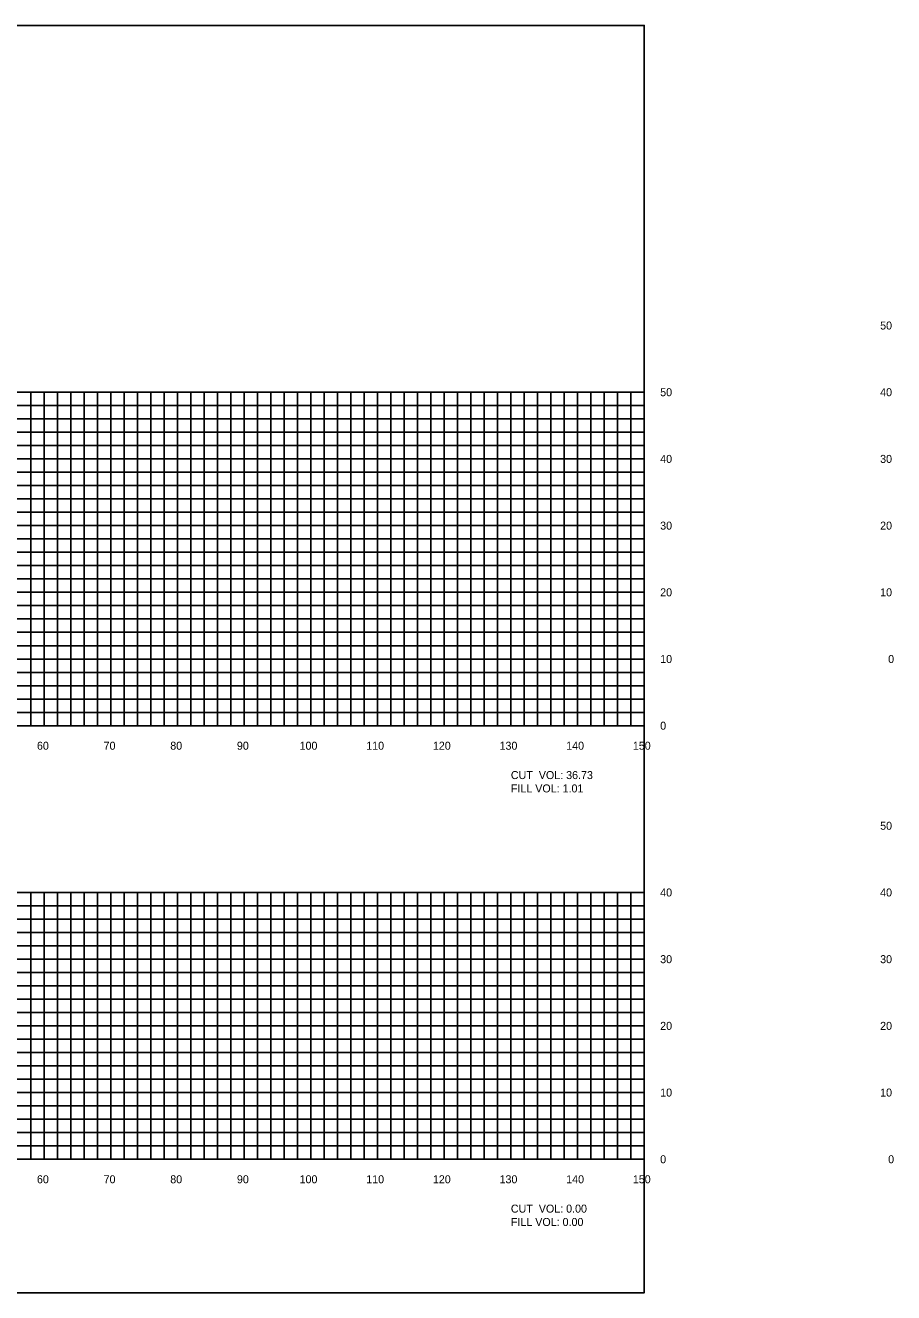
# Model space of a CAD drawing. Extents: x 1797652 to 1804145, y 245981 to 250269.
# Drawn here: x 1802348.2 to 1802478.4, y 250079.4 to 250269.4 of the extents above; entities that cross this region are included whole.
import ezdxf

# ---------------------------------------------------------------- set-up
doc = ezdxf.new("R2010")
doc.units = 0
for name, color, linetype in [('10', 7, 'Continuous'), ('31', 7, 'Continuous'), ('60', 7, 'Continuous'), ('ANNO-TXT', 7, 'Continuous'), ('Level 62', 7, 'Continuous')]:
    doc.layers.add(name, color=color, linetype=linetype)

msp = doc.modelspace()

# ---------------------------------------------------------------- linework, layer by layer
msp.add_lwpolyline([(1802141, 250079.43), (1802441, 250079.43), (1802441, 250269.43), (1802141, 250269.43)], close=True)
at = {"layer": '60'}
for p, q in [((1802441, 250164.43), (1802441, 250214.43)), ((1802441.06, 250214.43), (1802441, 250214.43)), ((1802441.06, 250204.43), (1802441, 250204.43)), ((1802441.06, 250194.43), (1802441, 250194.43)), ((1802441.06, 250184.43), (1802441, 250184.43)), ((1802441.06, 250174.43), (1802441, 250174.43)), ((1802141, 250164.43), (1802441, 250164.43)), ((1802351, 250164.37), (1802351, 250164.43)), ((1802361, 250164.37), (1802361, 250164.43)), ((1802371, 250164.37), (1802371, 250164.43)), ((1802381, 250164.37), (1802381, 250164.43)), ((1802391, 250164.37), (1802391, 250164.43)), ((1802401, 250164.37), (1802401, 250164.43)), ((1802411, 250164.37), (1802411, 250164.43)), ((1802421, 250164.37), (1802421, 250164.43)), ((1802431, 250164.37), (1802431, 250164.43)), ((1802441, 250164.37), (1802441, 250164.43)), ((1802441.06, 250164.43), (1802441, 250164.43)), ((1802441, 250099.43), (1802441, 250139.43)), ((1802441.06, 250139.43), (1802441, 250139.43)), ((1802441.06, 250129.43), (1802441, 250129.43)), ((1802441.06, 250119.43), (1802441, 250119.43)), ((1802441.06, 250109.43), (1802441, 250109.43)), ((1802141, 250099.43), (1802441, 250099.43)), ((1802351, 250099.37), (1802351, 250099.43)), ((1802361, 250099.37), (1802361, 250099.43)), ((1802371, 250099.37), (1802371, 250099.43)), ((1802381, 250099.37), (1802381, 250099.43)), ((1802391, 250099.37), (1802391, 250099.43)), ((1802401, 250099.37), (1802401, 250099.43)), ((1802411, 250099.37), (1802411, 250099.43)), ((1802421, 250099.37), (1802421, 250099.43)), ((1802431, 250099.37), (1802431, 250099.43)), ((1802441, 250099.37), (1802441, 250099.43)), ((1802441.06, 250099.43), (1802441, 250099.43))]:
    msp.add_line(p, q, dxfattribs=at)
at = {"layer": 'Level 62'}
for p, q in [((1802141, 250214.43), (1802441, 250214.43)), ((1802349, 250164.43), (1802349, 250214.43)), ((1802351, 250164.43), (1802351, 250214.43)), ((1802353, 250164.43), (1802353, 250214.43)), ((1802355, 250164.43), (1802355, 250214.43)), ((1802357, 250164.43), (1802357, 250214.43)), ((1802359, 250164.43), (1802359, 250214.43)), ((1802361, 250164.43), (1802361, 250214.43)), ((1802363, 250164.43), (1802363, 250214.43)), ((1802365, 250164.43), (1802365, 250214.43)), ((1802367, 250164.43), (1802367, 250214.43)), ((1802369, 250164.43), (1802369, 250214.43)), ((1802371, 250164.43), (1802371, 250214.43)), ((1802373, 250164.43), (1802373, 250214.43)), ((1802375, 250164.43), (1802375, 250214.43)), ((1802377, 250164.43), (1802377, 250214.43)), ((1802379, 250164.43), (1802379, 250214.43)), ((1802381, 250164.43), (1802381, 250214.43)), ((1802383, 250164.43), (1802383, 250214.43)), ((1802385, 250164.43), (1802385, 250214.43)), ((1802387, 250164.43), (1802387, 250214.43)), ((1802389, 250164.43), (1802389, 250214.43)), ((1802391, 250164.43), (1802391, 250214.43)), ((1802393, 250164.43), (1802393, 250214.43)), ((1802395, 250164.43), (1802395, 250214.43)), ((1802397, 250164.43), (1802397, 250214.43)), ((1802399, 250164.43), (1802399, 250214.43)), ((1802401, 250164.43), (1802401, 250214.43)), ((1802403, 250164.43), (1802403, 250214.43)), ((1802405, 250164.43), (1802405, 250214.43)), ((1802407, 250164.43), (1802407, 250214.43)), ((1802409, 250164.43), (1802409, 250214.43)), ((1802411, 250164.43), (1802411, 250214.43)), ((1802413, 250164.43), (1802413, 250214.43)), ((1802415, 250164.43), (1802415, 250214.43)), ((1802417, 250164.43), (1802417, 250214.43)), ((1802419, 250164.43), (1802419, 250214.43)), ((1802421, 250164.43), (1802421, 250214.43)), ((1802423, 250164.43), (1802423, 250214.43)), ((1802425, 250164.43), (1802425, 250214.43)), ((1802427, 250164.43), (1802427, 250214.43)), ((1802429, 250164.43), (1802429, 250214.43)), ((1802431, 250164.43), (1802431, 250214.43)), ((1802433, 250164.43), (1802433, 250214.43)), ((1802435, 250164.43), (1802435, 250214.43)), ((1802437, 250164.43), (1802437, 250214.43)), ((1802439, 250164.43), (1802439, 250214.43)), ((1802441, 250164.43), (1802441, 250214.43)), ((1802141, 250212.43), (1802441, 250212.43)), ((1802141, 250210.43), (1802441, 250210.43)), ((1802141, 250208.43), (1802441, 250208.43)), ((1802141, 250206.43), (1802441, 250206.43)), ((1802141, 250204.43), (1802441, 250204.43)), ((1802141, 250202.43), (1802441, 250202.43)), ((1802141, 250200.43), (1802441, 250200.43)), ((1802141, 250198.43), (1802441, 250198.43)), ((1802141, 250196.43), (1802441, 250196.43)), ((1802141, 250194.43), (1802441, 250194.43)), ((1802141, 250192.43), (1802441, 250192.43)), ((1802141, 250190.43), (1802441, 250190.43)), ((1802141, 250188.43), (1802441, 250188.43)), ((1802141, 250186.43), (1802441, 250186.43)), ((1802141, 250184.43), (1802441, 250184.43)), ((1802141, 250182.43), (1802441, 250182.43)), ((1802141, 250180.43), (1802441, 250180.43)), ((1802141, 250178.43), (1802441, 250178.43)), ((1802141, 250176.43), (1802441, 250176.43)), ((1802141, 250174.43), (1802441, 250174.43)), ((1802141, 250172.43), (1802441, 250172.43)), ((1802141, 250170.43), (1802441, 250170.43)), ((1802141, 250168.43), (1802441, 250168.43)), ((1802141, 250166.43), (1802441, 250166.43)), ((1802141, 250164.43), (1802441, 250164.43)), ((1802141, 250139.43), (1802441, 250139.43)), ((1802349, 250099.43), (1802349, 250139.43)), ((1802351, 250099.43), (1802351, 250139.43)), ((1802353, 250099.43), (1802353, 250139.43)), ((1802355, 250099.43), (1802355, 250139.43)), ((1802357, 250099.43), (1802357, 250139.43)), ((1802359, 250099.43), (1802359, 250139.43)), ((1802361, 250099.43), (1802361, 250139.43)), ((1802363, 250099.43), (1802363, 250139.43)), ((1802365, 250099.43), (1802365, 250139.43)), ((1802367, 250099.43), (1802367, 250139.43)), ((1802369, 250099.43), (1802369, 250139.43)), ((1802371, 250099.43), (1802371, 250139.43)), ((1802373, 250099.43), (1802373, 250139.43)), ((1802375, 250099.43), (1802375, 250139.43)), ((1802377, 250099.43), (1802377, 250139.43)), ((1802379, 250099.43), (1802379, 250139.43)), ((1802381, 250099.43), (1802381, 250139.43)), ((1802383, 250099.43), (1802383, 250139.43)), ((1802385, 250099.43), (1802385, 250139.43)), ((1802387, 250099.43), (1802387, 250139.43)), ((1802389, 250099.43), (1802389, 250139.43)), ((1802391, 250099.43), (1802391, 250139.43)), ((1802393, 250099.43), (1802393, 250139.43)), ((1802395, 250099.43), (1802395, 250139.43)), ((1802397, 250099.43), (1802397, 250139.43)), ((1802399, 250099.43), (1802399, 250139.43)), ((1802401, 250099.43), (1802401, 250139.43)), ((1802403, 250099.43), (1802403, 250139.43)), ((1802405, 250099.43), (1802405, 250139.43)), ((1802407, 250099.43), (1802407, 250139.43)), ((1802409, 250099.43), (1802409, 250139.43)), ((1802411, 250099.43), (1802411, 250139.43)), ((1802413, 250099.43), (1802413, 250139.43)), ((1802415, 250099.43), (1802415, 250139.43)), ((1802417, 250099.43), (1802417, 250139.43)), ((1802419, 250099.43), (1802419, 250139.43)), ((1802421, 250099.43), (1802421, 250139.43)), ((1802423, 250099.43), (1802423, 250139.43)), ((1802425, 250099.43), (1802425, 250139.43)), ((1802427, 250099.43), (1802427, 250139.43)), ((1802429, 250099.43), (1802429, 250139.43)), ((1802431, 250099.43), (1802431, 250139.43)), ((1802433, 250099.43), (1802433, 250139.43)), ((1802435, 250099.43), (1802435, 250139.43)), ((1802437, 250099.43), (1802437, 250139.43)), ((1802439, 250099.43), (1802439, 250139.43)), ((1802441, 250099.43), (1802441, 250139.43)), ((1802141, 250137.43), (1802441, 250137.43)), ((1802141, 250135.43), (1802441, 250135.43)), ((1802141, 250133.43), (1802441, 250133.43)), ((1802141, 250131.43), (1802441, 250131.43)), ((1802141, 250129.43), (1802441, 250129.43)), ((1802141, 250127.43), (1802441, 250127.43)), ((1802141, 250125.43), (1802441, 250125.43)), ((1802141, 250123.43), (1802441, 250123.43)), ((1802141, 250121.43), (1802441, 250121.43)), ((1802141, 250119.43), (1802441, 250119.43)), ((1802141, 250117.43), (1802441, 250117.43)), ((1802141, 250115.43), (1802441, 250115.43)), ((1802141, 250113.43), (1802441, 250113.43)), ((1802141, 250111.43), (1802441, 250111.43)), ((1802141, 250109.43), (1802441, 250109.43)), ((1802141, 250107.43), (1802441, 250107.43)), ((1802141, 250105.43), (1802441, 250105.43)), ((1802141, 250103.43), (1802441, 250103.43)), ((1802141, 250101.43), (1802441, 250101.43)), ((1802141, 250099.43), (1802441, 250099.43))]:
    msp.add_line(p, q, dxfattribs=at)

# ---------------------------------------------------------------- texts
at = {"layer": '10'}
for s, p in [('60', (1802349.9, 250160.83)), ('70', (1802359.9, 250160.83)), ('80', (1802369.9, 250160.83)), ('90', (1802379.9, 250160.83)), ('100', (1802389.3, 250160.83)), ('110', (1802399.3, 250160.83)), ('120', (1802409.3, 250160.83)), ('130', (1802419.3, 250160.83)), ('140', (1802429.3, 250160.83)), ('150', (1802439.3, 250160.83)), ('60', (1802349.9, 250095.83)), ('70', (1802359.9, 250095.83)), ('80', (1802369.9, 250095.83)), ('90', (1802379.9, 250095.83)), ('100', (1802389.3, 250095.83)), ('110', (1802399.3, 250095.83)), ('120', (1802409.3, 250095.83)), ('130', (1802419.3, 250095.83)), ('140', (1802429.3, 250095.83)), ('150', (1802439.3, 250095.83))]:
    msp.add_text(s, height=1.2, dxfattribs=at).set_placement(p)
at = {"layer": '31'}
for s, p in [('50', (1802476.4, 250223.83)), ('50', (1802443.4, 250213.83)), ('40', (1802476.4, 250213.83)), ('40', (1802443.4, 250203.83)), ('30', (1802476.4, 250203.83)), ('30', (1802443.4, 250193.83)), ('20', (1802476.4, 250193.83)), ('20', (1802443.4, 250183.83)), ('10', (1802476.4, 250183.83)), ('10', (1802443.4, 250173.83)), ('0', (1802477.6, 250173.83)), ('0', (1802443.4, 250163.83)), ('50', (1802476.4, 250148.83)), ('40', (1802443.4, 250138.83)), ('40', (1802476.4, 250138.83)), ('30', (1802443.4, 250128.83)), ('30', (1802476.4, 250128.83)), ('20', (1802443.4, 250118.83)), ('20', (1802476.4, 250118.83)), ('10', (1802443.4, 250108.83)), ('10', (1802476.4, 250108.83)), ('0', (1802443.4, 250098.83)), ('0', (1802477.6, 250098.83))]:
    msp.add_text(s, height=1.2, dxfattribs=at).set_placement(p)
at = {"layer": 'ANNO-TXT'}
for s, p in [('CUT  VOL: 36.73', (1802421, 250156.43)), ('FILL VOL: 1.01', (1802421, 250154.43)), ('CUT  VOL: 0.00', (1802421, 250091.43)), ('FILL VOL: 0.00', (1802421, 250089.43))]:
    msp.add_text(s, height=1.2, dxfattribs=at).set_placement(p)

doc.saveas('drawing.dxf')
